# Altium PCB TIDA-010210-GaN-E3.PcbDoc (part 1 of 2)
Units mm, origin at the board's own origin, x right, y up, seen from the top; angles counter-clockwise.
Board outline 75 x 60 mm, 4 copper layers (Top Layer, MidLayer1, MidLayer2, Bottom Layer), stack 1.554 mm thick; 107 components, 49 nets, 409 pads, 513 vias.
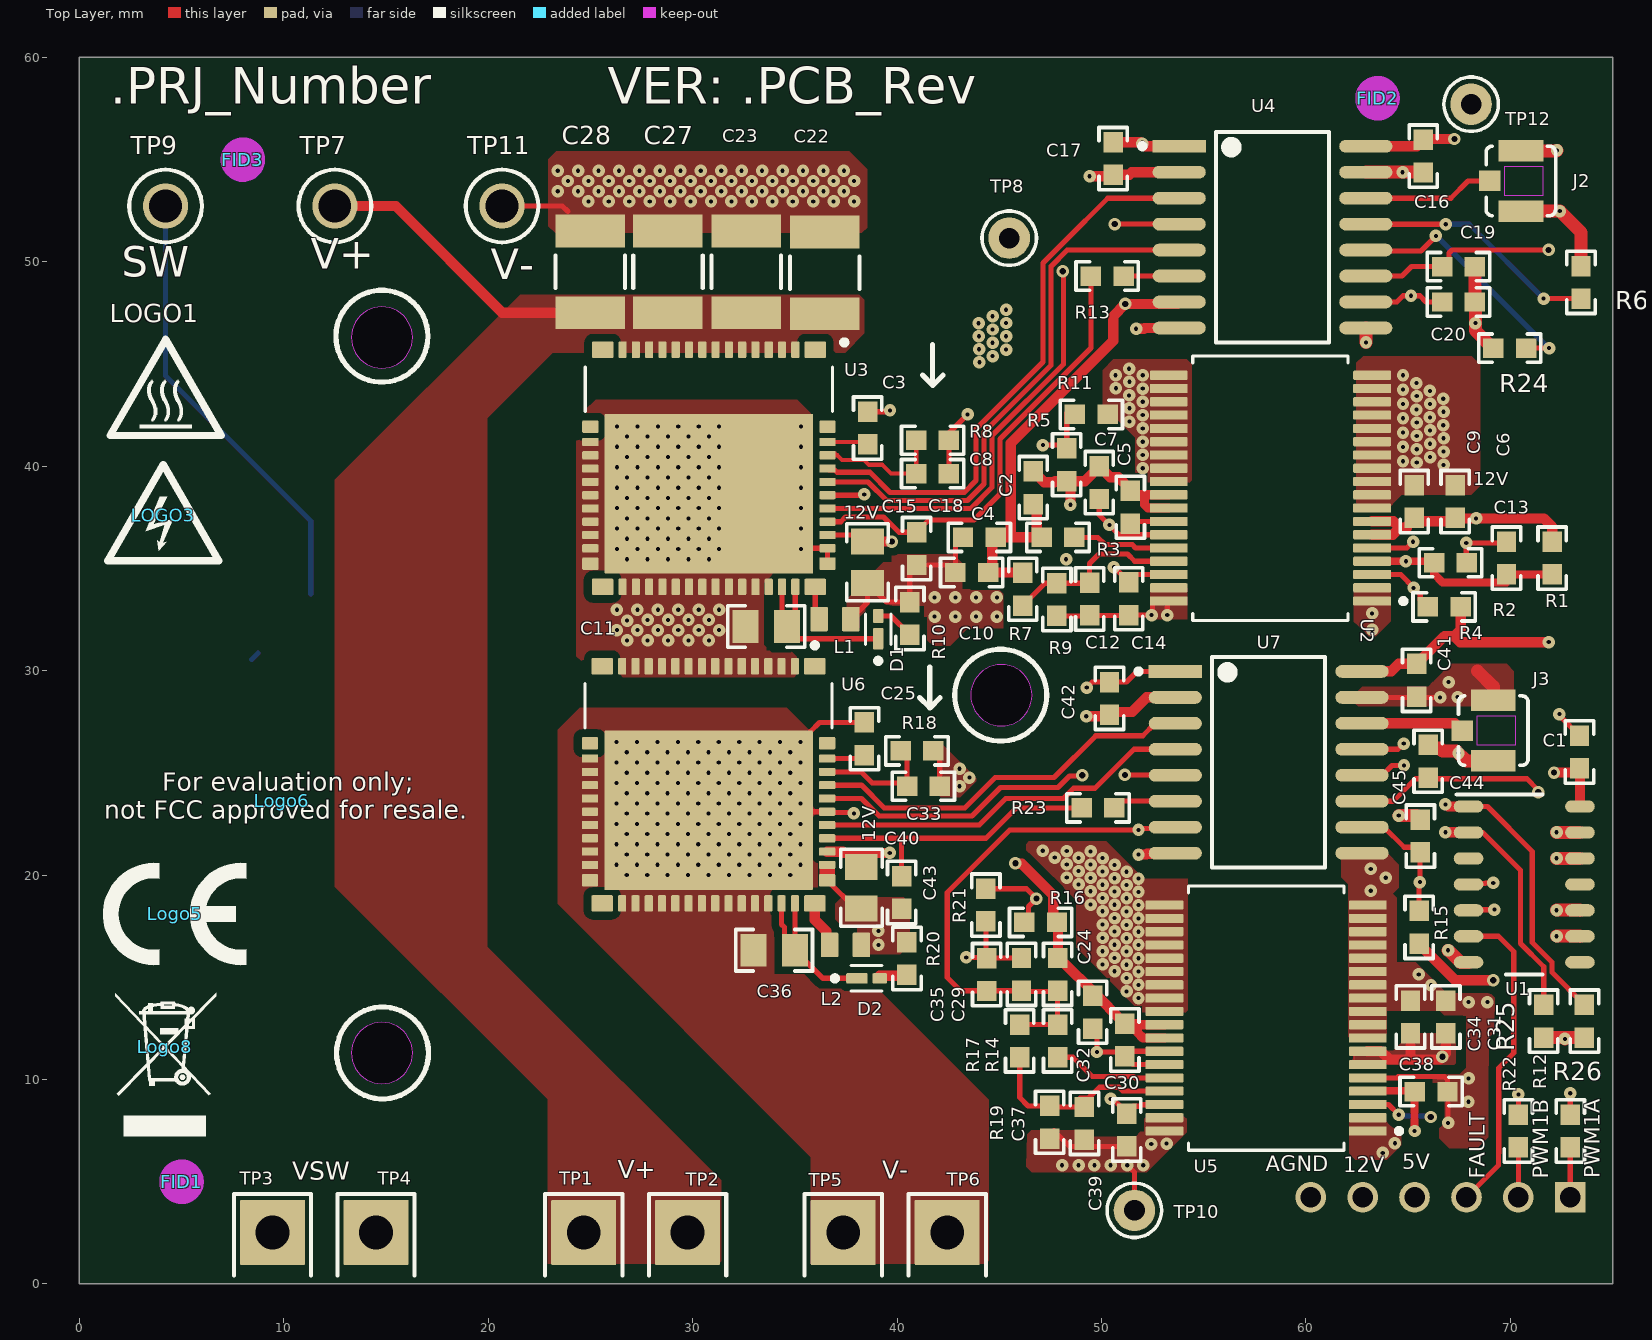
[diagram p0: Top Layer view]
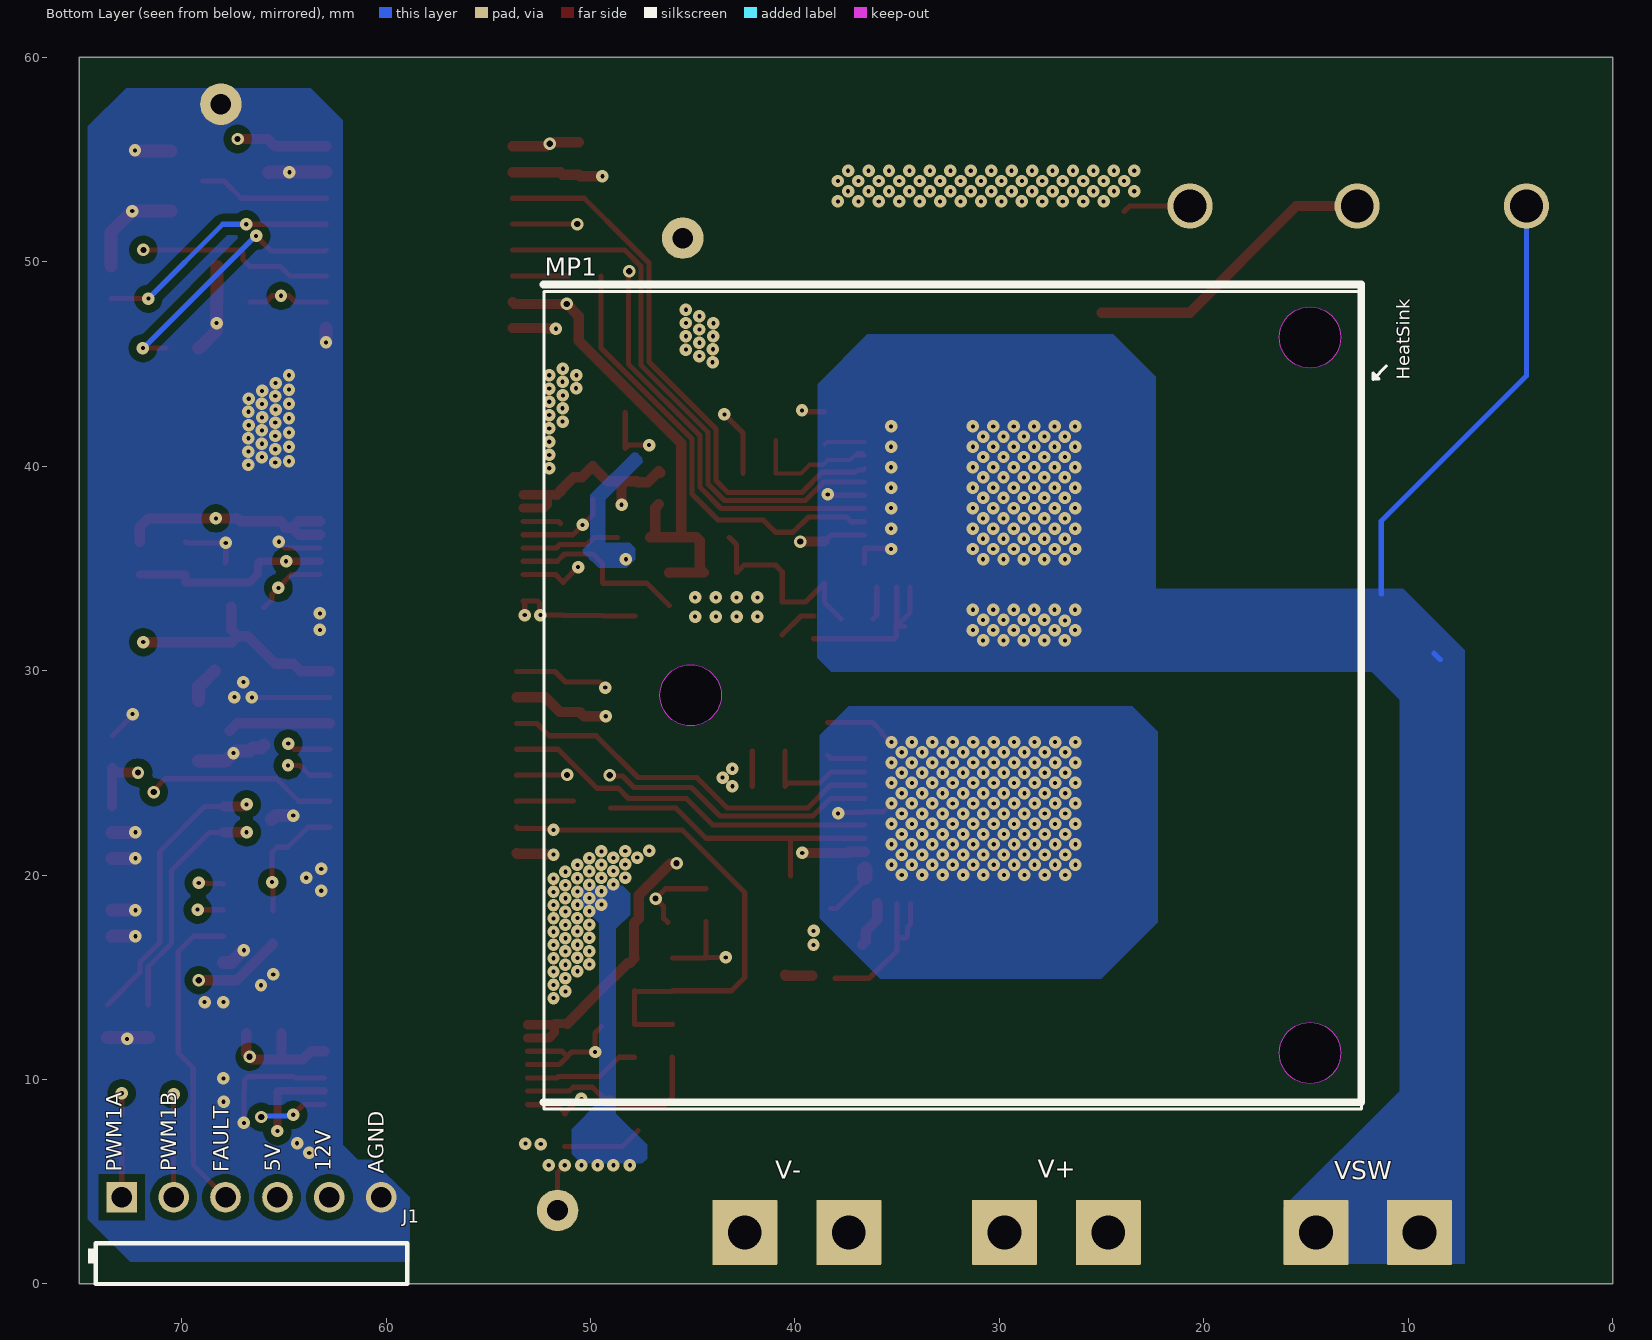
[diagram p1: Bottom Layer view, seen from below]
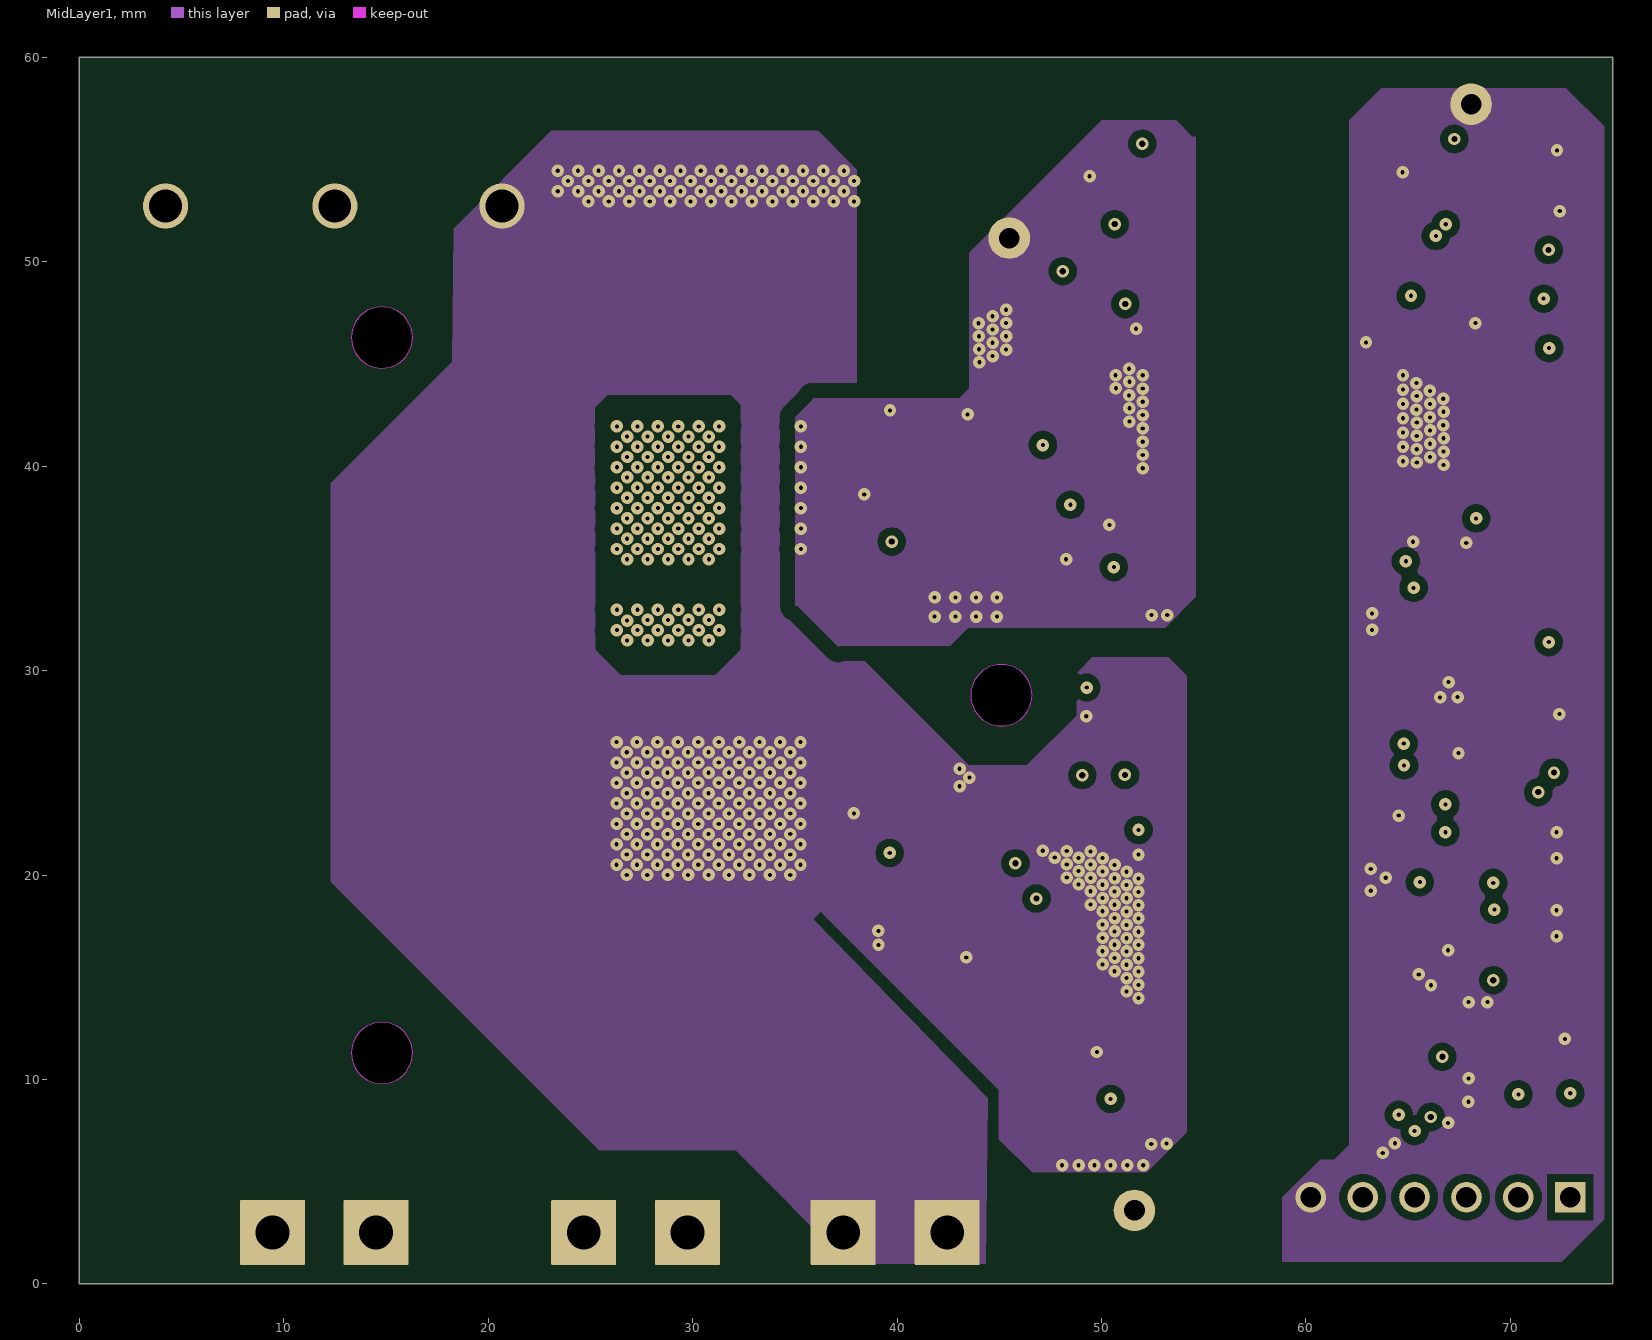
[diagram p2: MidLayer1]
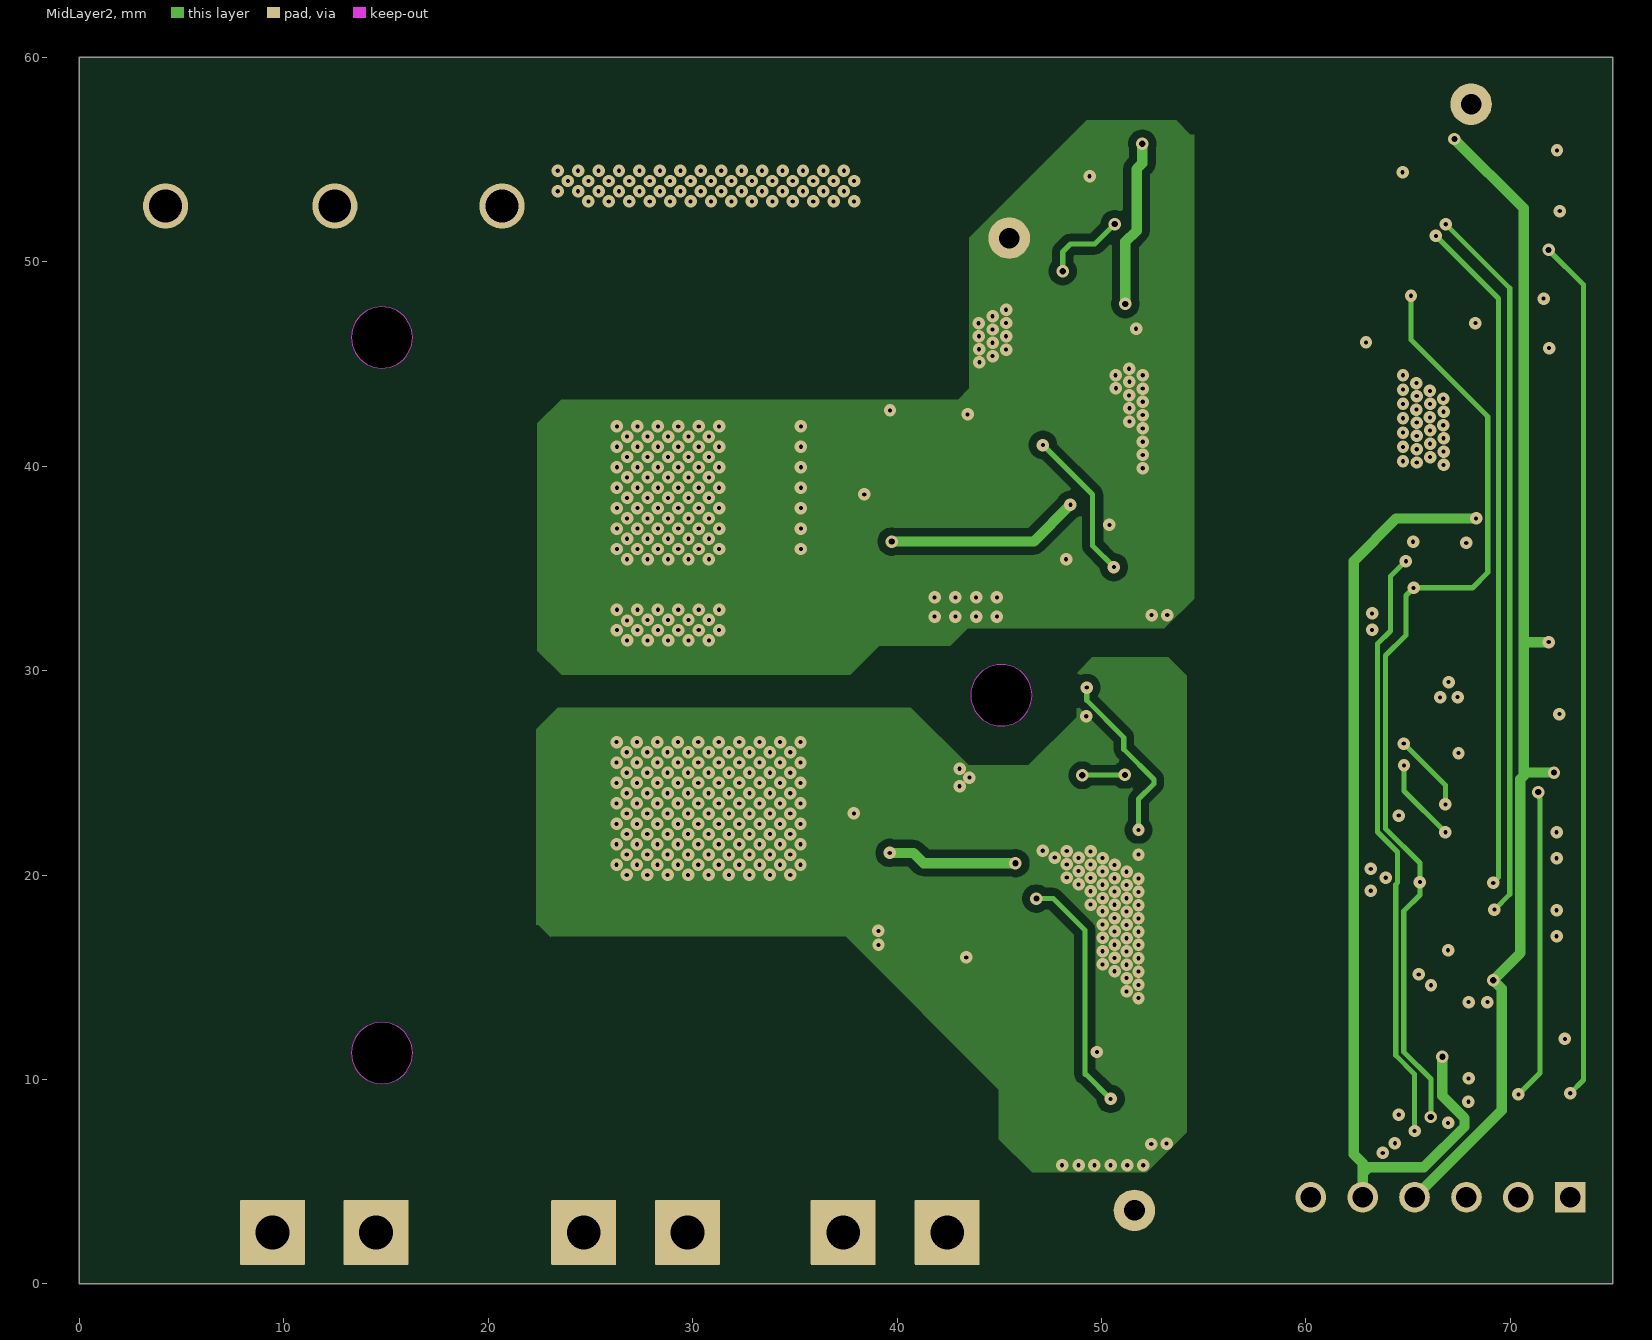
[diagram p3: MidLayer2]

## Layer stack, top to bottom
Top Solder: solder mask 0.0102, Solder Resist, Dk 3.5
Top Layer: signal copper 0.0711
Dielectric1: core 0.254, FR-4 High Tg, Dk 4.8
MidLayer1: signal copper 0.0711
Dielectric2: prepreg 0.762, FR-4 High Tg, Dk 4.8
MidLayer2: signal copper 0.0711
Dielectric3: core 0.254, FR-4 High Tg, Dk 4.8
Bottom Layer: signal copper 0.0711
Bottom Solder: solder mask 0.0102, Solder Resist, Dk 3.5

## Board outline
0,0 0,60 75,60 75,0
cut-out: 13.3,46.3 ccw(c14.8,46.3) 14.8,44.8 ccw(c14.8,46.3) 16.3,46.3 ccw(c14.8,46.3) 14.8,47.8 ccw(c14.8,46.3)
cut-out: 13.3,11.3 ccw(c14.8,11.3) 14.8,9.8 ccw(c14.8,11.3) 16.3,11.3 ccw(c14.8,11.3) 14.8,12.8 ccw(c14.8,11.3)
cut-out: 43.6,28.8 ccw(c45.1,28.8) 45.1,27.3 ccw(c45.1,28.8) 46.6,28.8 ccw(c45.1,28.8) 45.1,30.3 ccw(c45.1,28.8)

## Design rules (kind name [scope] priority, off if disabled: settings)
AcuteAngle [All] p1: minimum=4.50000000000000E+0001 checktracksonly=FALSE
AssemblyTestPointUsage [All] p1: valid=2
Clearance "Basic ISO to HV" [InNetClass('ISO') vs InNetClass('HV_PLUS')  or InNetClass('HV_MINUS') or InNetClass('HV_BRIDGE_POINT')] p1: gap=4 ignorepadtopadclearanceinfootprint=FALSE
Clearance "HVPLUS TO HVMINUS" [InNetClass('HV_PLUS') vs InNetClass('HV_MINUS')] p2: gap=2.2 ignorepadtopadclearanceinfootprint=FALSE
Clearance "HVPHVN to BR" [InNetClass('HV_PLUS')  or InNetClass('HV_MINUS') vs InNetClass('HV_BRIDGE_POINT')] p3: gap=0.762 ignorepadtopadclearanceinfootprint=FALSE
Clearance Clearance_BoardEdge_MountingHoles [OnCopper and InComponentClass('Mounting Holes') vs IsKeepOut] p4: gap=0.508 ignorepadtopadclearanceinfootprint=FALSE except(0: Arc-Hole Track-Hole SMDPad-Hole THPad-Hole Via-Hole Fill-Hole Poly-Hole Region-Hole Text-Hole)
Clearance Clearance_HV2_Mid1 [OnMid And InNetClass('VSWNET') vs (OnMultiLayer Or OnMid) And Not InNetClass('VSWNET')] p5: gap=0.508 ignorepadtopadclearanceinfootprint=FALSE except(0: Arc-Hole Track-Hole SMDPad-Hole THPad-Hole Via-Hole Fill-Hole Poly-Hole Region-Hole Text-Hole)
Clearance Clearance_HV2_Mid2 [(OnMultiLayer Or OnMid) And InNetClass('VSWNET') vs OnMid And Not InNetClass('VSWNET')] p6: gap=0.508 ignorepadtopadclearanceinfootprint=FALSE except(0: Arc-Hole Track-Hole SMDPad-Hole THPad-Hole Via-Hole Fill-Hole Poly-Hole Region-Hole Text-Hole)
Clearance Clearance_HV1_Mid1 [(OnMultiLayer Or OnMid) And InNetClass('VHV') vs OnMid And Not InNetClass('VHV')] p7: gap=0.508 ignorepadtopadclearanceinfootprint=FALSE except(0: Arc-Hole Track-Hole SMDPad-Hole THPad-Hole Via-Hole Fill-Hole Poly-Hole Region-Hole Text-Hole)
Clearance Clearance_HV1_Mid2 [OnMid And InNetClass('VHV') vs (OnMultiLayer Or OnMid) And Not InNetClass('VHV')] p8: gap=0.508 ignorepadtopadclearanceinfootprint=FALSE except(0: Arc-Hole Track-Hole SMDPad-Hole THPad-Hole Via-Hole Fill-Hole Poly-Hole Region-Hole Text-Hole)
Clearance Clearance_HV1 [InNetClass('VHV') vs NOT InNetClass('VHV')] p9: gap=1.524 ignorepadtopadclearanceinfootprint=FALSE except(0: Arc-Hole Track-Hole SMDPad-Hole THPad-Hole Via-Hole Fill-Hole Poly-Hole Region-Hole Text-Hole; 1.016: THPad-Fill THPad-Poly THPad-Region)
Clearance "Clearance_Poly to All" [inpoly] p10: gap=0.381 ignorepadtopadclearanceinfootprint=FALSE
Clearance [All] p11: gap=0.14 ignorepadtopadclearanceinfootprint=FALSE except(0: Arc-Arc Arc-SMDPad Arc-THPad Arc-Hole Track-Hole SMDPad-Hole THPad-Hole Via-Hole Fill-Hole Poly-Hole Region-Hole Text-Hole)
ComponentClearance ComponentClearance_Shunt [InComponentClass('Header') vs InComponentClass('Shunt')] p1: gap=0 collisioncheckmode=3 verticalgap=0 showdistances=FALSE
ComponentClearance ComponentClearance_MountingHoles_FiducialMarks [InComponentClass('Mounting Holes') vs InComponentClass('FiducialMark')] p2: gap=1.27 collisioncheckmode=3 verticalgap=0.254 showdistances=FALSE
ComponentClearance ComponentClearance_Logo [InComponentClass('Logo')] p3: gap=0 collisioncheckmode=3 verticalgap=0.254 showdistances=FALSE
ComponentClearance ComponentClearance_ScrewToNut [(HasFootprint('NY PMS 440 0025 PH')) vs (HasFootprint('Keystone_1902C'))] p4: gap=0.127 collisioncheckmode=3 verticalgap=0.254 showdistances=FALSE
ComponentClearance ComponentClearance_MountingHoles [InComponentClass('Mounting Holes')] p5: gap=6.35 collisioncheckmode=3 verticalgap=2540 showdistances=FALSE
ComponentClearance ComponentClearance_SmallPassives [HasFootprint('0201*') or HasFootprint('0402*') or HasFootprint('0508') or HasFootprint('0603*') or HasFootprint('0612') or HasFootprint('0805*') or HasFootprint('0815*') or HasFootprint('0830*') or HasFootprint('1206*') or HasFootprint('1210*') or HasFootprint('1808*') or HasFootprint('1812*') or HasFootprint('1825*') or HasFootprint('2010*') or HasFootprint('2220*') or HasFootprint('2225*') or HasFootprint('2512*') or HasFootprint('2728*') or HasFootprint('3518*') vs HasFootprint('0201*') or HasFootprint('0402*') or HasFootprint('0508') or HasFootprint('0603*') or HasFootprint('0612') or HasFootprint('0805*') or HasFootprint('0815*') or HasFootprint('0830*') or HasFootprint('1206*') or HasFootprint('1210*') or HasFootprint('1808*') or HasFootprint('1812*') or HasFootprint('1825*') or HasFootprint('2010*') or HasFootprint('2220*') or HasFootprint('2225*') or HasFootprint('2512*') or HasFootprint('2728*') or HasFootprint('3518*')] p6: gap=0.381 collisioncheckmode=3 verticalgap=0.254 showdistances=FALSE
ComponentClearance ComponentClearance_THtoSMT [IsThruComponent vs IsSMTComponent] p7: gap=0.762 collisioncheckmode=3 verticalgap=0.762 showdistances=FALSE
ComponentClearance ComponentClearance_THtoTH [IsThruComponent vs IsThruComponent] p8: gap=0 collisioncheckmode=3 verticalgap=0.254 showdistances=FALSE
ComponentClearance [All] p9: gap=0.381 collisioncheckmode=3 verticalgap=0.254 showdistances=FALSE
DiffPairsRouting [All] p1: maxlimit=2.54 minlimit=0.254 mostfreqgap=0.254 toplayer_minwidth=0.381 toplayer_maxwidth=0.381 toplayer_prefwidth=0.381 midlayer1_minwidth=0.381 midlayer1_maxwidth=0.381 midlayer1_prefwidth=0.381 midlayer2_minwidth=0.381 midlayer2_maxwidth=0.381 midlayer2_prefwidth=0.381 bottomlayer_minwidth=0.381 bottomlayer_maxwidth=0.381 bottomlayer_prefwidth=0.381 maxuncoupledlength=25.4
FabricationTestPointUsage TestPointUsage [All] p1: valid=2 allowmultiple=FALSE
FabricationTestpoint Testpoint [All] p1: side=3 testpointundercomponent=TRUE minsize=1.016 maxsize=2.54 preferedsize=1.524 minholesize=0 maxholesize=1.016 preferedholesize=0.813 testpointgrid=0.025 allowsidetop=TRUE allowsidebottom=TRUE usegrid=TRUE gridtolerance=0
FanoutControl Fanout_LCC [IsLCC] p1: bgadir=Out bgaviamode=Centered fanoutstyle=Auto fanoutdirection=Alternating viagrid=0.025 // Fanout_LCC (Default Rule)
FanoutControl Fanout_BGA [IsBGA] p2: bgadir=Out bgaviamode=Centered fanoutstyle=Auto fanoutdirection=Alternating viagrid=0.025 // Fanout_BGA (Default Rule)
FanoutControl Fanout_Default [All] p4: bgadir=Out bgaviamode=Centered fanoutstyle=Auto fanoutdirection=Alternating viagrid=0.025 // Fanout_Default (Default Rule)
FanoutControl Fanout_Small [(CompPinCount < 5)] p5: bgadir=Out bgaviamode=Centered fanoutstyle=Auto fanoutdirection=OutThenIn viagrid=0.025 // Fanout_Small (Default Rule)
HoleSize [All] p1: absolutevalues=TRUE maxlimit=6.375 minlimit=0.152 maxpercent=80.000 minpercent=20.000
MinimumAnnularRing MinimumAnnularRing_ThermalPadVias [IsVia and InAnyComponent] p1 off: minimumring=0.127
MinimumAnnularRing [IsVia] p2 off: minimumring=0.127
MinimumSolderMaskSliver MinimumSolderMaskSliver_Logo [InComponentClass('Logo') vs InComponentClass('Logo')] p1: minsoldermaskwidth=0.018
MinimumSolderMaskSliver [All] p2: minsoldermaskwidth=0.1
PlaneConnect [All] p1: planeconnectstyle=Relief reliefexpansion=0.254 reliefentries=4 reliefconductorwidth=0.254 reliefairgap=0.254
PolygonConnect [All] p1: connectstyle=Direct reliefconductorwidth=0.254 reliefentries=4 polygonreliefangle="90 Angle" airgapwidth=0.254
RoutingVias ThermalPadVias [IsVia and InAnyComponent] p1: holewidth=0.203 width=0.406 viastyle="Through Hole" minholewidth=0.203 minwidth=0.406 maxholewidth=0.203 maxwidth=0.406
RoutingVias [All] p2: holewidth=0.305 width=0.61 viastyle="Through Hole" minholewidth=0.152 minwidth=0.254 maxholewidth=1.016 maxwidth=1.651
SMDToCorner [All] p1: distance=30000
SilkToSilkClearance [All] p1: silktosilkclearance=0
SilkToSolderMaskClearance SilkscreenOverComponentPads [IsPad] p1: minsilkscreentomaskgap=0.127 clearancetoexposedcopper=TRUE
SolderMaskExpansion [All] p1: expansion=0.05 istentingtop=FALSE
Width [All] p1: maxlimit=25.4 minlimit=0.152 preferedwidth=0.635 toplayer_prefwidth=0.305 midlayer1_prefwidth=0.254 midlayer2_prefwidth=0.254 minimp=50.000000 maximp=50.000000 favimp=50.000000 checkconnectedcopper=TRUE
16 further rules are at their usual default settings.

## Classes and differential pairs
net class HV_PLUS: High_Rail NetU3_1 NetU3_16
net class HV_MINUS: 5V_LS 12V_LS Low_Rail NetC25_2 NetC33_2 NetC36_2 NetC37_1 NetC39_1 NetC43_1 NetD2_2 NetL2_2 NetR14_1 NetR23_1 NetU5_17 NetU5_28 NetU5_54 NetU6_48 NetU6_50 NetU6_51
net class ISO: 5V_ISO 12V_ISO EN_Supply_Driver F\A\U\L\T\_\H\S\_\I\S\O\ F\A\U\L\T\_\L\S\_\I\S\O\ GND_ISO NetC19_1 NetC20_1 NetC44_1 NetJ1_3 NetU1_3 NetU1_8 NetU1_11 O\C\_\H\S\_\I\S\O\ O\C\_\L\S\_\I\S\O\ PWM_HS_ISO PWM_LS_ISO TEMP_HS_ISO TEMP_LS_ISO
net class HV_BRIDGE_POINT: 5V_HS 12V_HS NetC3_2 NetC8_2 NetC11_2 NetC12_1 NetC14_1 NetC18_1 NetD1_2 NetL1_2 NetR3_1 NetR13_1 NetU3_17 NetU3_28 NetU3_48 NetU3_50 NetU3_51 NetU3_54 NetU5_1 NetU5_16 SW_Rail
component class U_Half_Bridge: C2 C3 C4 C5 C6 C7 C8 C9 C10 C11 C12 C13 C14 C15 C16 C17 C18 C19 C20 C22 C23 C24 C25 C27 C28 C29 C30 C31 C32 C33 C34 C35 C36 C37 C38 C39 C40 C41 C42 C43 C44 C45 D1 D2 "Heat Sink1" L1 L2 R3 R4 R5 R7 R8 R9 R10 R11 R12 R13 R14 R15 R16 R17 R18 R19 R20 R21 R22 R23 "Thermal Pad1" TP7 TP8 TP9 TP10 TP11 TP12 U2 U3 U4 U5 U6 U7
component class AssemblyNote: ZZ1 ZZ2 ZZ3
component class FiducialMark: FID1 FID2 FID3
component class "Cover Sheet-Pg1": !PCB C1 FID1 FID2 FID3 HS1 J1 J2 J3 LOGO1 LOGO3 Logo5 Logo6 Logo8 MP1 R1 R2 R6 R24 R25 R26 TIM1 TP1 TP2 TP3 TP4 TP5 TP6 U1 ZZ1 ZZ2 ZZ3
component class Header: J1

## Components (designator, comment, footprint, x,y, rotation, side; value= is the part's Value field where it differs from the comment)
C1 "06033C104JAT2A" 0603 73.381,26.018 r90 top value=0.1uF
C2 "C1608X6S1C155K080AC" 0603 46.657,38.952 r270 top value=1.5uF
C3 "06033C104JAT2A" 0603 38.555,41.867 r270 top value=0.1uF
C4 "06033C104JAT2A" 0603 44.024,36.519 r180 top value=0.1uF
C5 "06033C104JAT2A" 0603 51.411,37.994 r270 top value=0.1uF
C6 "GRM188C71E225KE11D" 0603 67.297,38.271 r90 top value=2.2uF
C7 "GRM188C71E225KE11D" 0603 49.889,39.198 r270 top value=2.2uF
C8 "C0603C102F3GACTU" 0603 41.736,39.639 r180 top value=1000pF
C9 "GRM1885C1H151JA01D" 0603 65.297,38.271 r90 top value=150pF
C10 "GRM188C71E225KE11D" 0603 43.649,34.802 r180 top value=2.2uF
C11 "GRM21BR71E225KA73L" 0805_HV 33.596,32.166 r0 top value=2.2uF
C12 "C0603X332K5RACTU" 0603 49.414,33.503 r270 top value=3300pF
C13 "SR0603X7R103K1NT95(F)#M123A" 0603 67.069,35.277 r0 top value=0.01uF
C14 "C0603X332K5RACTU" 0603 51.329,33.518 r270 top value=3300pF
C15 "GRM219B31E106MA12" 0805_HV 38.555,35.301 r270 top value=10uF
C16 "06033C104JAT2A" 0603 65.738,55.169 r270 top value=0.1uF
C17 "06033C104JAT2A" 0603 50.564,55.05 r270 top value=0.1uF
C18 "C0603C221K5GACTU" 0603 40.955,35.969 r270 top value=220pF
C19 "C0603C221K5GACTU" 0603 67.462,49.763 r0 top value=220pF
C20 "SR0603X7R103K1NT95(F)#M123A" 0603 67.462,48.033 r0 top value=0.01uF
C22 "C1812W104KDRACTU" 1812_254 36.461,49.463 r90 top value=0.1uF
C23 "C1812W104KDRACTU" 1812_254 32.629,49.51 r90 top value=0.1uF
C24 "C1608X6S1C155K080AC" 0603 47.853,15.146 r270 top value=1.5uF
C25 "06033C104JAT2A" 0603 38.401,26.669 r270 top value=0.1uF
C27 "C1812W104KDRACTU" 1812_254 28.792,49.51 r90 top value=0.1uF
C28 "C1812W104KDRACTU" 1812_254 24.982,49.51 r90 top value=0.1uF
C29 "06033C104JAT2A" 0603 46.084,15.146 r90 top value=0.1uF
C30 "06033C104JAT2A" 0603 51.138,11.935 r270 top value=0.1uF
C31 "GRM188C71E225KE11D" 0603 66.841,13.064 r90 top value=2.2uF
C32 "GRM188C71E225KE11D" 0603 49.563,13.291 r270 top value=2.2uF
C33 "C0603C102F3GACTU" 0603 41.286,24.349 r180 top value=1000pF
C34 "GRM1885C1H151JA01D" 0603 65.114,13.064 r90 top value=150pF
C35 "GRM188C71E225KE11D" 0603 44.382,15.131 r90 top value=2.2uF
C36 "GRM21BR71E225KA73L" 0805_HV 33.984,16.322 r0 top value=2.2uF
C37 "C0603X332K5RACTU" 0603 49.163,7.856 r270 top value=3300pF
C38 "SR0603X7R103K1NT95(F)#M123A" 0603 66.122,9.413 r0 top value=0.01uF
C39 "C0603X332K5RACTU" 0603 51.234,7.529 r270 top value=3300pF
C40 "GRM219B31E106MA12" 0805_HV 38.251,19.381 r270 top value=10uF
C41 "06033C104JAT2A" 0603 65.415,29.529 r270 top value=0.1uF
C42 "06033C104JAT2A" 0603 50.39,28.644 r270 top value=0.1uF
C43 "C0603C221K5GACTU" 0603 40.218,19.151 r270 top value=220pF
C44 "C0603C221K5GACTU" 0603 65.977,25.568 r90 top value=220pF
C45 "SR0603X7R103K1NT95(F)#M123A" 0603 65.598,21.909 r90 top value=0.01uF
D1 "KG DELLS1.22-JGKH-24" "FP-KG DELLS1.22-JGKH-24_0603-MFG" 39.075,32.033 r90 top
D2 "KG DELLS1.22-JGKH-24" "FP-KG DELLS1.22-JGKH-24_0603-MFG" 38.505,14.95 r0 top
FID1 "Fiducial" Fiducial6.4-20 5,5 r0 top
FID2 "Fiducial" Fiducial6.4-20 63.5,58 r0 top
FID3 "Fiducial" Fiducial6.4-20 8,55 r0 top
J1 "90121-0766" Molex_90121-0766 66.581,4.242 r180 bottom
J2 "U.FL-R-SMT-1(01)" CONN_UFL-R-SMT-1 70.51,53.956 r0 top
J3 "U.FL-R-SMT-1(01)" CONN_UFL-R-SMT-1 69.162,27.068 r0 top
L1 "74404020100" WE-LQS_2010 36.961,32.522 r180 top value=10uH
L2 "74404020100" WE-LQS_2010 37.476,16.582 r180 top value=10uH
LOGO1 "CAUTION HOT SURFACE" IEC_HotSurface_Small 4.216,43.863 r0 top
LOGO3 "DANGER HIGH VOLTAGE" IEC_HighVoltage_Small 4.102,37.61 r0 top
Logo5 "CE Mark" CE_Mark_5mm 4.661,18.098 r0 top
Logo6 "FCC disclaimer" FCC_disclaimer_stacked 9.898,23.645 r0 top
Logo8 "WEEE logo" WEEE_Minimum 4.178,11.593 r0 top
MP1 "APF40-40-13CB/A01" FP-APF40-40-13CB-A01_HEATSINK_40MM0_40MM0-MFG 32.275,28.55 r180 bottom
R1 "RC0603FR-0712KL" 0603 72.046,35.507 r90 top value=12.0k
R2 "RC0603FR-072K7L" 0603 69.81,35.507 r270 top value=2.70k
R3 "RC0603JR-071KL" 0603 47.872,36.52 r180 top value=1.0k
R4 "RC0603FR-0712KL" 0603 66.761,33.125 r180 top value=12.0k
R5 "M55342K12B10E0T" 0603 48.296,40.073 r90 top value=10.0k
R6 "CR0603-JW-472GLF" 0603 73.455,48.993 r270 top value=4.7k
R7 "M55342K12B10E0T" 0603 46.147,33.983 r90 top value=10.0k
R8 "RC0603FR-0733KL" 0603 41.736,41.271 r0 top value=33.0k
R9 "M55342K12B10E0T" 0603 47.817,33.478 r90 top value=10.0k
R10 "RC0603JR-075K6L" 0603 40.623,32.553 r270 top value=5.6k
R11 "RC0603FR-072K61L" 0603 49.5,42.534 r180 top value=2.61k
R12 "RC0603FR-0756RL" 0603 72.931,7.482 r90 top value=56.0
R13 "RC0603FR-0756RL" 0603 50.278,49.303 r180 top value=56.0
R14 "RC0603JR-071KL" 0603 47.853,11.891 r90 top value=1.0k
R15 "RC0603FR-0712KL" 0603 65.534,17.446 r270 top value=12.0k
R16 "M55342K12B10E0T" 0603 47.022,17.692 r180 top value=10.0k
R17 "M55342K12B10E0T" 0603 45.996,11.891 r90 top value=10.0k
R18 "RC0603FR-0733KL" 0603 40.97,26.074 r0 top value=33.0k
R19 "M55342K12B10E0T" 0603 47.462,7.912 r90 top value=10.0k
R20 "RC0603JR-075K6L" 0603 40.48,15.921 r270 top value=5.6k
R21 "RC0603FR-072K61L" 0603 44.341,18.532 r90 top value=2.61k
R22 "RC0603FR-0756RL" 0603 70.391,7.482 r90 top value=56.0
R23 "RC0603FR-0756RL" 0603 49.826,23.289 r180 top value=56.0
R24 "CR0603-JW-472GLF" 0603 69.969,45.78 r0 top value=4.7k
R25 "CR0603-JW-472GLF" 0603 71.63,12.853 r90 top value=4.7k
R26 "CR0603-JW-472GLF" 0603 73.622,12.853 r90 top value=4.7k
TP1 "3620-2-32-15-00-00-08-0" Mill-Max_3620-2-32-xx-00-00-08-0 24.671,0 r0 top
TP2 "3620-2-32-15-00-00-08-0" Mill-Max_3620-2-32-xx-00-00-08-0 29.751,0 r0 top
TP3 "3620-2-32-15-00-00-08-0" Mill-Max_3620-2-32-xx-00-00-08-0 9.449,0 r0 top
TP4 "3620-2-32-15-00-00-08-0" Mill-Max_3620-2-32-xx-00-00-08-0 14.511,0 r0 top
TP5 "3620-2-32-15-00-00-08-0" Mill-Max_3620-2-32-xx-00-00-08-0 37.363,0 r0 top
TP6 "3620-2-32-15-00-00-08-0" Mill-Max_3620-2-32-xx-00-00-08-0 42.451,0 r0 top
TP7 "5005" Keystone5005 12.497,52.73 r0 top
TP8 "5001" Keystone5001 45.484,51.158 r90 top
TP9 "5008" Keystone5008 4.216,52.73 r0 top
TP10 "5001" Keystone5001 51.606,3.601 r90 top
TP11 "5006" Keystone5006 20.676,52.73 r0 top
TP12 "5001" Keystone5001 68.079,57.71 r90 top
U1 "SN74AS21D" D0014A_N 70.677,19.546 r0 top
U2 "UCC14150DWNQ1" DWN0036A-MFG 58.261,38.927 r180 top locked
U3 "LMG3422R030" RQZ0054A-MFG-NV 30.796,39.9 r270 top locked
U4 "ISO7741FDW" FP-DW0016A-IPC_A 58.363,51.208 r0 top locked
U5 "UCC14150DWNQ1" DWN0036A-MFG 58.051,13.007 r180 top locked
U6 "LMG3422R030" RQZ0054A-MFG-NV 30.775,24.415 r270 top locked
U7 "ISO7741FDW" FP-DW0016A-IPC_A 58.175,25.518 r0 top locked
ZZ1 "These assemblies are ESD sensitive, ESD precautions shall be observed." AssemblyNote 1.778,67.963 r0 top
ZZ2 "These assemblies must be clean and free from flux and all contaminants. Use of no clean flux is not acceptable." AssemblyNote 1.778,65.677 r0 top
ZZ3 "These assemblies must comply with workmanship standards IPC-A-610 Class 2, unless otherwise specified." AssemblyNote 1.778,62.756 r0 top

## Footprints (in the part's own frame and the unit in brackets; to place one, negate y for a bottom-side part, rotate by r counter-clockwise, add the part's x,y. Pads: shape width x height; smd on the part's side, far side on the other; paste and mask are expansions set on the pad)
0603 [mm] "0603 from SM-752 data"
  rect 1x0.95 smd: 1(-0.8,0) 2(0.8,0)
  silkscreen extent -1.52,-0.69 1.52,0.69, body extent -0.87,-0.47 0.87,0.47, height 1
0805_HV [mil] "0805 with 30mil clearance between pads"
  rect 50x63 smd: 1(-40,0) 2(40,0)
  silkscreen extent -74,-40 74,40, body extent -43,-29 43,29, height 57
1812_254 [mm] "SMD, 2-Leads, Body 4.8x3.4mm"
  rect 1.6x3.4 smd: 1(-2,0) 2(2,0)
  silkscreen extent -0.8,-1.7 0.8,1.7, body extent -2.4,-1.7 2.4,1.7, height 2.54
AssemblyNote [mm] "Assembly Note"
CE_Mark_5mm [mm] "Minimum text height for CE Mark"
  silkscreen extent -3.5,-2.5 3.5,2.5
CONN_UFL-R-SMT-1 [mm] "Hirose recommended land pattern http://www.hirose.co.jp/cataloge_hp/e32119372.pdf 2009.2"
  rect 1.05x1 smd paste-0.1 mask-0.1: 1(-1.525,0)
  rect 2.2x1.05 smd paste-2 mask-2: 2(0,1.475) 3(0,-1.475)
  rect 2x0.9 on Top Paste: 2(0,1.5) 3(0,-1.5)
  rect 2x0.9 on Top Solder: 2(0,1.5) 3(0,-1.5)
  Top Layer keep-out region: -0.8,-0.7 1.1,-0.7 1.1,0.7 -0.8,0.7
  silkscreen extent -1.7,-1.7 1.7,1.7, body extent -1.55,-1.5 1.55,1.5, height 1.27
D0014A_N [mm] "SOIC, 14-Leads, Body 8.7x3.9mm, Pitch 1.27mm, IPC Medium Density"
  oval 1.45x0.6 smd: 1(-2.725,3.81) 2(-2.725,2.54) 3(-2.725,1.27) 4(-2.725,0) 5(-2.725,-1.27) 6(-2.725,-2.54) 7(-2.725,-3.81) 8(2.725,-3.81) 9(2.725,-2.54) 10(2.725,-1.27) 11(2.725,0) 12(2.725,1.27) 13(2.725,2.54) 14(2.725,3.81)
  silkscreen extent -3.3,-4.4 0.9,4.4, body extent -3.02,-4.32 3.02,4.32, height 1.6
DWN0036A-MFG [mm]
  rrect22% 1.85x0.45 smd paste+0 mask+0: 1(-4.975,5.525) 2(-4.975,4.875) 3(-4.975,4.225) 4(-4.975,3.575) 5(-4.975,2.925) 6(-4.975,2.275) 7(-4.975,1.625) 8(-4.975,0.975) 9(-4.975,0.325) 10(-4.975,-0.325) 11(-4.975,-0.975) 12(-4.975,-1.625) 13(-4.975,-2.275) 14(-4.975,-2.925) 15(-4.975,-3.575) 16(-4.975,-4.225) 17(-4.975,-4.875) 18(-4.975,-5.525) 19(4.975,-5.525) 20(4.975,-4.875) 21(4.975,-4.225) 22(4.975,-3.575) 23(4.975,-2.925) 24(4.975,-2.275) 25(4.975,-1.625) 26(4.975,-0.975) 27(4.975,-0.325) 28(4.975,0.325) 29(4.975,0.975) 30(4.975,1.625) 31(4.975,2.275) 32(4.975,2.925) 33(4.975,3.575) 34(4.975,4.225) 35(4.975,4.875) 36(4.975,5.525)
  silkscreen extent -6.63,-6.47 3.8,6.47, body extent -6,-6.72 6,6.72, height 0.25
FCC_disclaimer_stacked [mm]
Fiducial6.4-20 [mm]
  round 0.635 smd mask+0.683: 1(0,0)
  Top Layer keep-out circle w1.178: c0,0 r0.5
FP-APF40-40-13CB-A01_HEATSINK_40MM0_40MM0-MFG [mm]
  silkscreen extent -20,-20 20,20, body extent -20,-20 20,20, height 12.7
FP-DW0016A-IPC_A [mm]
  rect 2.603x0.622 smd paste+0 mask+0: 1(-4.565,4.445)
  rrect100% 2.603x0.622 smd paste+0 mask+0: 2(-4.565,3.175) 3(-4.565,1.905) 4(-4.565,0.635) 5(-4.565,-0.635) 6(-4.565,-1.905) 7(-4.565,-3.175) 8(-4.565,-4.445) 9(4.565,-4.445) 10(4.565,-3.175) 11(4.565,-1.905) 12(4.565,-0.635) 13(4.565,0.635) 14(4.565,1.905) 15(4.565,3.175) 16(4.565,4.445)
  silkscreen extent -6.49,-5.15 2.76,5.15, body extent -6.37,-5.65 6.37,5.65, height 0.25
"FP-KG DELLS1.22-JGKH-24_0603-MFG" [mm]
  rrect20% 1.05x0.5 smd paste-1000 mask+0: 1(-0.47,0)
  rrect20% 0.7x0.5 smd paste-1000 mask+0: 2(0.645,0)
  silkscreen extent -1.67,-0.63 0.75,0.63, body extent -0.8,-0.4 0.8,0.4, height 0.7
IEC_HighVoltage_Small [mm]
  silkscreen extent -2.72,-2.24 2.72,2.47
IEC_HotSurface_Small [mm]
  silkscreen extent -2.72,-2.36 2.72,2.35
Keystone5001 [mil] "For Keystone 500x miniature loop terminals"
  round 80 hole 40: 1(0,0)
  silkscreen extent -52,-52 52,52, body extent -49,-49 49,49, height 182
Keystone5005 [mil] "Keystone Compact loops"
  round 87 hole 63: 1(0,0)
  silkscreen extent -70,-70 70,70, body extent -63,-63 62,63, height 225
Keystone5006 [mil] "Keystone Compact loops"
  round 87 hole 63: 1(0,0)
  silkscreen extent -70,-70 70,70, body extent -63,-63 62,63, height 225
Keystone5008 [mil] "Keystone Compact loops"
  round 87 hole 63: 1(0,0)
  silkscreen extent -70,-70 70,70, body extent -63,-63 62,63, height 225
Mill-Max_3620-2-32-xx-00-00-08-0 [mm] "PCB Pin, 0.04\" DIA, R/A, Edge-Mount"
  rrect3% 3.18x3.18 hole 1.65: 1(0,2.52)
  silkscreen extent -1.89,0.41 1.89,4.41, body extent -1.59,-5.06 1.59,4.11, height 0.65
Molex_90121-0766 [mm] "Header, 2.54mm, 6x1, R/A, TH"
  rect 1.5x1.5 hole 1: 1(-6.35,0)
  round 1.5 hole 1: 2(-3.81,0) 3(-1.27,0) 4(1.27,0) 5(3.81,0) 6(6.35,0)
  silkscreen extent -8,-4.25 7.62,-2.25, body extent -7.62,-11 7.62,0.32, height 3.63
RQZ0054A-MFG-NV [mm]
  rrect13% 0.8x1.05 smd paste+0 mask+0: 1(-5.8,5.2) 16(-5.8,-5.2) 28(5.8,-5.2) 43(5.8,5.2)
  rrect25% 0.8x0.4 smd paste+0 mask+0: 2(-5.8,4.225) 3(-5.8,3.575) 4(-5.8,2.925) 5(-5.8,2.275) 6(-5.8,1.625) 7(-5.8,0.975) 8(-5.8,0.325) 9(-5.8,-0.325) 10(-5.8,-0.975) 11(-5.8,-1.625) 12(-5.8,-2.275) 13(-5.8,-2.925) 14(-5.8,-3.575) 15(-5.8,-4.225) 29(5.8,-4.225) 30(5.8,-3.575) 31(5.8,-2.925) 32(5.8,-2.275) 33(5.8,-1.625) 34(5.8,-0.975) 35(5.8,-0.325) 36(5.8,0.325) 37(5.8,0.975) 38(5.8,1.625) 39(5.8,2.275) 40(5.8,2.925) 41(5.8,3.575) 42(5.8,4.225)
  rrect17% 0.6x0.8 smd paste+0 mask+0: 17(-2.035,-5.8) 27(4.665,-5.8) 44(4.665,5.8) 54(-2.035,5.8)
  rrect25% 0.4x0.8 smd paste+0 mask+0: 18(-1.285,-5.8) 19(-0.635,-5.8) 20(0.015,-5.8) 21(0.665,-5.8) 22(1.315,-5.8) 23(1.965,-5.8) 24(2.615,-5.8) 25(3.265,-5.8) 26(3.915,-5.8) 45(3.915,5.8) 46(3.265,5.8) 47(2.615,5.8) 48(1.965,5.8) 49(1.315,5.8) 50(0.665,5.8) 51(0.015,5.8) 52(-0.635,5.8) 53(-1.285,5.8)
  rrect1% 7.8x10.2 smd paste-1000 mask+0: 55(1.25,0)
  silkscreen extent -6.28,-6.05 -2.78,6.74, body extent -6.3,-6.3 6.3,6.3, height 0.25
WE-LQS_2010 [mm] "SMD, 2-Leads, Body 2x1.6mm"
  rrect12% 0.85x1.2 smd: 1(-0.775,0) 2(0.775,0)
  body extent -1,-0.82 1,0.8, height 0.98
WEEE_Minimum [mm] "WEEElie bin"
  silkscreen extent -2.42,-4.38 2.52,2.65

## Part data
C1 C3 C4 C5 C16 C17 C25 C29 C30 C41 C42: library part CMP-0006752-5, "CAP, CERM, 0.1 uF, 25 V, +/- 5%, X7R, 0603", Cap_Case=0603, Manufacturer=AVX, Supplier Part Number 1=478-3713-1-ND, TempCo=X7R, Tolerance_%=5%, Value1="0.05 ohm", Value2=25V, ValueDisplayed=0.1uF
C2 C24: library part CMP-0007025-4, "CAP, CERM, 1.5 uF, 16 V, +/- 10%, X6S, 0603", Cap_Case=0603, Manufacturer=TDK, Supplier Part Number 1=445-14211-1-ND, TempCo=X6S, Tolerance_%=10%, Value1="0.009039 ohm", Value2=16V, ValueDisplayed=1.5uF
C6 C7 C10 C31 C32 C35: library part CMP-0075366-3, "CAP, CERM, 2.2 µF, 25 V,+/- 10%, X7S, 0603", Cap_Case=0603, Manufacturer=MuRata, Supplier Part Number 1=490-12732-1-ND, TempCo=X7S, Tolerance_%=10%, Value2=25V, ValueDisplayed=2.2µF
C8 C33: library part CMP-0080092-1, "CAP, CERM, 1000 pF, 25 V,+/- 1%, C0G/NP0, 0603", Cap_Case=0603, Manufacturer=Kemet, Supplier Part Number 1=399-7825-1-ND, TempCo=C0G/NP0, Tolerance_%=1%, Value2=25V, ValueDisplayed=1000pF
C9 C34: library part CMP-0007185-4, "CAP, CERM, 150 pF, 50 V, +/- 5%, C0G/NP0, 0603", Cap_Case=0603, Manufacturer=MuRata, Supplier Part Number 1=490-1431-1-ND, TempCo=C0G/NP0, Tolerance_%=5%, Value1=Unknown, Value2=50V, ValueDisplayed=150pF
C11 C36: library part CMP-0008342-2, "CAP, CERM, 2.2 uF, 25 V, +/- 10%, X7R, 0805", Alternate Manufacturer=Murata, Alternate PartNumber=GRM219R61E225KA12D, Cap_Case=0805, Manufacturer=MuRata, Supplier Part Number 1=490-3331-1-ND, TempCo=X7R, Tolerance_%=10%, Value1="0.005 ohm", Value2=25V, ValueDisplayed=2.2uF
C12 C14 C37 C39: library part CMP-0006985-4, "CAP, CERM, 3300 pF, 50 V, +/- 10%, X7R, 0603", Cap_Case=0603, Manufacturer=Kemet, Supplier Part Number 1=399-5339-1-ND, TempCo=X7R, Tolerance_%=10%, Value1=Unknown, Value2=50V, ValueDisplayed=3300pF
C13 C20 C38 C45: library part CMP-0079721-1, "CAP, CERM, 0.01 µF, 25 V,+/- 10%, X7R, 0603", Cap_Case=0603, Manufacturer="Presidio Components", TempCo=X7R, Tolerance_%=10%, Value2=25V, ValueDisplayed=0.01µF
C15 C40: library part CMP-0008183-2, "CAP, CERM, 10 uF, 25 V, +/- 20%, B, 0805", Cap_Case=0805, Manufacturer=MuRata, TempCo=B, Tolerance_%=20%, Value1=Unknown, Value2=25V, ValueDisplayed=10uF
C18 C19 C43 C44: library part CMP-0006894-4, "CAP, CERM, 220 pF, 50 V, +/- 10%, C0G/NP0, 0603", Cap_Case=0603, Manufacturer=Kemet, Supplier Part Number 1=399-1065-1-ND, TempCo=C0G/NP0, Tolerance_%=10%, Value1=Unknown, Value2=50V, ValueDisplayed=220pF
C22 C23 C27 C28: library part CMP-0009326-2, "CAP, CERM, 0.1 uF, 1000 V, +/- 10%, X7R, 1812", Cap_Case=1812, Manufacturer=Kemet, Supplier Part Number 1=399-6523-1-ND, TempCo=X7R, Tolerance_%=10%, Value1=Unknown, Value2=1000V, ValueDisplayed=0.1uF
D1 D2: library part CMP-0093310-1, "Standard LEDs - SMD Green TOPLED E 1608", Color=Green, Forward Current=2mA, Manufacturer="Osram Opto", Mouser Part Number=720-KGDELLS122A4849, Operating Temperature Range="-40°C to +110°C"
FID1 FID2 FID3: library part CMP-0077181-1, "Fiducial mark.  There is nothing to buy or mount.", Manufacturer=N/A
J1: library part CMP-0055334-1, "Header, 2.54mm, 6x1, Gold, R/A, TH", Color=Black, Current_A=3A, Manufacturer=Molex, Supplier Part Number 1=WM8112-ND, Voltage_V=350V
J2 J3: library part CMP-0075320-1, "Receptacle, Ultra Miniature Coaxial, Male Pin, 50 ohm, SMT", Color=Beige, Manufacturer="Hirose Electric Co. Ltd.", Supplier Part Number 1=H122041-ND
L1 L2: library part CMP-0063789-1, "Inductor, 10 uH, 0.5 A, 0.85 ohm, SMD", Manufacturer="Wurth Elektronik", Value1="0.85 ohm", Value2=0.5A, ValueDisplayed=10uH
LOGO1: library part CMP-0074837-1, "IEC 61010-1 Hot Surface Warning"
LOGO3: library part CMP-0074835-1, "IEC 61010-1 High Voltage Warning"
Logo5: library part CMP-0074844-1
Logo6: library part CMP-0074847-1, "FCC_disclaimer"
Logo8: library part CMP-0074769-1
MP1: library part CMP-0093659-2, "Heat Sink Assorted (BGA, LGA, CPU, ASIC...) Aluminum - Top Mount", Digikey Part Number=294-1162-ND, Manufacturer=CTS, Mating Package=BGA, Mouser Part Number=774-APF404013CB/A01, Natural Thermal Resistance=9.9°C/W, Operating Temperature Range=to, Thermal Resistance Forced Air Flow=2.3°C/W
R1 R4 R15: library part CMP-0022779-5, "RES, 12.0 k, 1%, 0.1 W, 0603", Manufacturer=Yageo, Power_W=100mW, Supplier Part Number 1=311-12.0KHRCT-ND, TempCo="100 ppm/C", Tolerance_%=1%, Value2=0.1W, Value_Code=12k0, ValueDisplayed=12.0k
R2: library part CMP-0022996-5, "RES, 2.70 k, 1%, 0.1 W, 0603", Manufacturer=Yageo, Power_W=100mW, Supplier Part Number 1=311-2.70KHRCT-ND, TempCo="100 ppm/C", Tolerance_%=1%, Value2=0.1W, Value_Code=2k70, ValueDisplayed=2.70k
R3 R14: library part CMP-0025899-5, "RES, 1.0 k, 5%, 0.1 W, 0603", Manufacturer=Yageo, Power_W=100mW, Supplier Part Number 1=311-1.0KGRCT-ND, TempCo="100 ppm/C", Tolerance_%=5%, Value2=0.1W, Value_Code=1k00, ValueDisplayed=1.0k
R5 R7 R9 R16 R17 R19: library part CMP-0080488-1, "RES, 10.0 k, 1%, 0.1 W, 0603", Manufacturer="TT Electronics/IRC", Power_W=100mW, TempCo="100 ppm/C", Tolerance_%=1%, Value2=0.1W, Value_Code=10k0, ValueDisplayed=10.0k
R6 R24 R25 R26: library part CMP-0025696-3, "RES, 4.7 k, 5%, 0.1 W, 0603", Manufacturer=Bourns, Power_W=100mW, Supplier Part Number 1=CR0603-JW-472GLFCT-ND, TempCo="200 ppm/C", Tolerance_%=5%, Value2=0.1W, Value_Code=4k70, ValueDisplayed=4.7k
R8 R18: library part CMP-0023037-5, "RES, 33.0 k, 1%, 0.1 W, 0603", Manufacturer=Yageo, Power_W=100mW, Supplier Part Number 1=311-33.0KHRCT-ND, TempCo="100 ppm/C", Tolerance_%=1%, Value2=0.1W, Value_Code=33k0, ValueDisplayed=33.0k
R10 R20: library part CMP-0025933-5, "RES, 5.6 k, 5%, 0.1 W, 0603", Manufacturer=Yageo, Power_W=100mW, Supplier Part Number 1=311-5.6KGRCT-ND, TempCo="100 ppm/C", Tolerance_%=5%, Value2=0.1W, Value_Code=5k60, ValueDisplayed=5.6k
R11 R21: library part CMP-0022993-5, "RES, 2.61 k, 1%, 0.1 W, 0603", Manufacturer=Yageo, Power_W=100mW, Supplier Part Number 1=311-2.61KHRCT-ND, TempCo="100 ppm/C", Tolerance_%=1%, Value2=0.1W, Value_Code=2k61, ValueDisplayed=2.61k
R12 R13 R22 R23: library part CMP-0023188-5, "RES, 56.0, 1%, 0.1 W, 0603", Manufacturer=Yageo, Power_W=100mW, Supplier Part Number 1=311-56.0HRCT-ND, TempCo="100 ppm/C", Tolerance_%=1%, Value2=0.1W, Value_Code=56R0, ValueDisplayed=56.0
TP1 TP2 TP3 TP4 TP5 TP6: library part CMP-0055044-1, "PCB Pin, 0.04\" DIA, Edge-Mount", Manufacturer=Mill-Max, Supplier Part Number 1=ED1278-ND
TP7: library part CMP-0055142-1, "Test Point, Compact, Red, TH", Color=Red, Manufacturer=Keystone, Supplier Part Number 1=36-5005-ND
TP8 TP10 TP12: library part CMP-0055138-1, "Test Point, Miniature, Black, TH", Color=Black, Manufacturer=Keystone, Supplier Part Number 1=36-5001-ND
TP9: library part CMP-0055145-1, "Test Point, Compact, Orange, TH", Color=Orange, Manufacturer=Keystone, Supplier Part Number 1=36-5008-ND
TP11: library part CMP-0055143-1, "Test Point, Compact, Black, TH", Color=Black, Manufacturer=Keystone, Supplier Part Number 1=36-5006-ND
U1: library part CMP-0054374-1, "Dual 4-Input Positive-AND Gates, D0014A, TUBE", F @ Nom Voltage(Max)(Mhz)=125, Generic Part Number=SN74AS21, ICC @ Nom Voltage(Max)(mA)=0.0014, Manufacturer="Texas Instruments", Operating Temperature Range(C)="0 to 70", Rating=Catalog, tpd @ Nom Voltage(Max)(ns)=15, Voltage(Nom)(V)=5
U2 U5: library part CMP-0093317-1, "1W, 15V-Vin, 15V-Vout, High-Efficiency, >3 kVRMS Isolated DC-DC Converter", Manufacturer="Texas Instruments", Max Power Dissipation=540mW, Max Supply Voltage=27V, Min Supply Voltage=10V, Operating Temperature Range="-40°C to +150°C", Output Voltage=2.5-17V
U3 U6: library part CMP-0088545-3, "600-V 30-mΩ Integrated GaN Power Stage with Smart Driver", Manufacturer="Texas Instruments", Max Supply Voltage=18V, Min Supply Voltage=7.5V, Nominal Supply Current=13mA, Operating Temperature Range="-40°C to +125°C", Output Voltage=480V, Part Number=LMG3425R030RQZT
U4 U7: library part CMP-04872-000092-1, "DGTL ISO 5000VRMS 4CH GP 16SOIC", Case/Package=SOIC, Manufacturer="Texas Instruments", Max Operating Temperature=125°C, Max Supply Voltage=5.5V, Min Operating Temperature=-55°C, Min Supply Voltage=2.25V
ZZ1: library part CMP-0077236-1
ZZ2: library part CMP-0077237-1
ZZ3: library part CMP-0077238-1

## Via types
v1: diameter 0.61, hole 0.203, Top Layer to Bottom Layer, tented both sides, 497 vias
v2: diameter 0.61, hole 0.305, Top Layer to Bottom Layer, tented both sides, 16 vias

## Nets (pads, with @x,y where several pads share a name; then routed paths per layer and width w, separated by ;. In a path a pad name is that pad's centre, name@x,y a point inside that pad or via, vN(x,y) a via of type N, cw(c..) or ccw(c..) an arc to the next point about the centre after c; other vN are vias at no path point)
5V_HS: C2.2 C4.1 C10.1 C17.1 R3.2 R7.2 U4.1 U4.7 | length 35.5
  Top Layer w0.508: R7.2@46.147,34.783 46.128,34.802 44.653,34.802 C10.1@44.449,34.802 44.653,35.006 44.653,36.349 44.825,36.52 45.07,36.52 45.548,36.52 ; C2.2@46.657,38.152 46.838,37.971 46.838,36.729 R3.2@47.047,36.52 ; R3.2@47.072,36.52 R3.2@47.047,36.52 ; C17.1@50.564,55.85 51.897,55.85 51.969,55.778 v2(51.996,55.778) 52.024,55.778 52.149,55.653 U4.1@53.798,55.653 ; U4.7@53.798,48.033 53.702,47.937 v2(51.164,47.937) 50.575,47.348 50.575,46.141 45.558,41.123 45.558,36.53 45.548,36.52 ; 45.548,36.52 46.826,36.52 R3.2@47.047,36.52
  MidLayer2 w0.508: v2(51.164,47.937) 51.164,50.978 51.713,51.527 51.713,54.541 51.996,54.824 v2(51.996,55.778)
5V_ISO: C1.1 C16.1 C41.1 J1.4 R4.1 R15.2 U1.14 U4.16 U7.16 | length 82.1
  Top Layer w0.508: U7.16@62.74,29.963 64.175,29.963 64.542,30.329 C41.1@65.415,30.329 66.774,31.688 67.261,31.688 ; U4.16@62.929,55.653 65.422,55.653 65.492,55.723 65.517,55.723 65.738,55.944 C16.1@65.738,55.969 65.776,56.007 v2(67.261,56.007) ; R15.2@65.534,16.646 65.534,16.621 67.294,14.861 v2(69.162,14.861) ; R4.1@67.561,33.125 67.566,33.121 67.566,31.993 67.261,31.688 ; v1(71.874,31.396) 69.81,31.396 67.553,31.396 67.261,31.688 ; v2(72.133,25.018) 73.181,25.018 C1.1@73.381,25.218 73.402,25.197 U1.14@73.402,23.356
  MidLayer2 w0.508: J1.4@65.311,4.242 67.001,5.932 69.572,8.502 69.572,14.451 v2(69.162,14.861) 70.49,16.189 70.49,24.696 70.651,24.857 70.651,25.018 ; v2(67.261,56.007) 70.651,52.617 70.651,31.276 ; v1(71.874,31.396) 70.772,31.396 70.651,31.276 ; v2(72.133,25.018) 70.651,25.018 ; 70.651,25.018 70.651,31.276
5V_LS: C24.2 C29.1 C35.1 C42.1 R14.2 R17.2 U7.1 U7.7 | length 39.2
  Top Layer w0.254: R17.2@45.981,12.706 R17.2@45.996,12.691 R14.2@47.853,12.691 C24.2@47.853,14.306 ; C24.2@47.853,14.346 C24.2@47.853,14.306 ; v1(49.276,29.174) 49.547,29.444 C42.1@50.39,29.444 51.214,29.444 51.733,29.963 U7.1@53.609,29.963 ; U7.7@53.609,22.343 53.539,22.273 51.872,22.273 v1(51.808,22.209) 45.509,22.209 42.451,19.151 42.451,14.993 43.099,14.346 44.382,14.346 45.981,14.346 46.02,14.306 C24.2@47.853,14.306
  MidLayer2 w0.254: v1(49.276,29.174) 49.276,28.55 51.088,26.738 51.088,26.153 52.559,24.682 52.559,24.471 51.808,23.72 v1(51.808,22.209)
12V_HS: C2.1 C5.1 C7.1 C15.1 R5.1 U2.28 U2.29 U3.46 | length 23.6
  Top Layer w0.254: U3.46@36.596,36.635 38.237,36.635 C15.1@38.555,36.317
  Top Layer w0.45: C5.1@51.654,38.602 52.115,38.602 ; U2.29@53.286,37.952 52.279,37.952 52.095,38.136 52.095,38.583 52.115,38.602 ; U2.28@53.286,38.602 52.115,38.602
  Top Layer w0.508: C15.1@38.555,36.317 v2(39.734,36.317) ; C2.1@46.578,39.673 C2.1@46.657,39.752 47.186,39.223 47.694,39.223 47.745,39.273 R5.1@48.296,39.273 ; v1(48.479,38.114) 48.479,39.09 R5.1@48.296,39.273 ; C5.1@51.462,38.769 C5.1@51.462,38.794 ; C5.1@51.654,38.602 C5.1@51.462,38.794 ; R5.1@48.296,39.273 49.189,39.273 49.889,39.973 C7.1@49.889,39.998 50.418,39.469 50.812,39.469 51.462,38.819 C5.1@51.462,38.794
  MidLayer2 w0.508: v2(39.734,36.317) 46.682,36.317 v1(48.479,38.114)
12V_ISO: C6.1 C9.1 C31.1 C34.1 J1.5 R1.2 U2.6 U2.7 U5.6 U5.7 | length 65.9
  Top Layer w0.508: U5.7@63.026,11.382 63.668,11.382 64.068,10.982 65.114,10.982 ; U2.6@63.236,36.652 64.237,36.652 64.569,36.983 64.569,37 ; U2.7@63.236,37.302 64.266,37.302 64.569,37 ; C34.1@65.114,12.264 65.114,10.982 ; C31.1@66.841,12.264 66.841,11.28 v2(66.672,11.111) 66.543,10.982 65.114,10.982 ; R1.2@72.046,36.307 72.046,37.029 71.63,37.446 v1(68.324,37.446) 67.323,37.446 C6.1@67.297,37.471 67.128,37.302 65.153,37.302 64.923,37.072 64.923,37 64.569,37
  MidLayer2 w0.508: J1.5@62.771,4.242 62.771,5.416 ; v2(66.672,11.111) 66.672,9.202 67.656,8.218 67.755,8.119 67.755,7.698 65.771,5.714 63.069,5.714 62.771,5.416 ; v1(68.324,37.446) 64.424,37.446 62.335,35.356 62.335,6.34 62.771,5.903 62.771,5.416
12V_LS: C24.1 C30.1 C32.1 C40.1 R16.1 U5.28 U5.29 U6.46 | length 23.5
  Top Layer w0.45: C30.1@51.138,12.735 51.731,12.735 ; 51.765,12.7 51.765,12.296 52.029,12.032 U5.29@53.076,12.032 ; 51.784,12.682 U5.28@53.076,12.682
  Top Layer w0.508: U6.46@36.575,21.15 37.333,21.15 37.399,21.084 v1(39.637,21.084) ; v2(45.789,20.581) 45.808,20.562 46.091,20.562 46.801,19.853 47.642,19.011 47.642,17.872 R16.1@47.822,17.692 47.872,17.642 47.872,15.964 C24.1@47.853,15.946 47.853,15.921 48.074,15.7 48.173,15.7 49.563,14.31 C30.1@51.138,12.735
  MidLayer2 w0.508: v1(39.637,21.084) 40.797,21.084 41.299,20.581 v2(45.789,20.581)
EN_Supply_Driver: C13.1 C38.1 R1.1 R2.2 U2.4 U5.4 | length 43.5
  Top Layer w0.381: U5.4@63.026,9.432 63.041,9.447 65.287,9.447 C38.1@65.322,9.413 ; U2.4@63.236,35.352 v1(64.886,35.352) 66.194,35.352 C13.1@66.269,35.277 66.269,34.726 66.678,34.317 69.81,34.317 R2.2@69.81,34.707 R1.1@72.046,34.707 ; v1(65.311,7.482) C38.1@65.311,9.413
  MidLayer2 w0.254: v1(64.886,35.352) 64.868,35.352 64.136,34.619 64.136,31.945 63.503,31.313 63.503,22.108 64.474,21.137 64.474,19.631 64.389,19.547 64.389,11.184 65.311,10.262 v1(65.311,7.482)
F\A\U\L\T\_\H\S\_\I\S\O\: R6.2 U1.5 U4.13 | length 48.5
  Top Layer w0.254: U4.13@62.929,51.843 62.937,51.835 v1(66.84,51.835) ; U1.5@67.952,18.276 67.986,18.309 v1(69.217,18.309) ; v1(71.625,48.202) 73.446,48.202 R6.2@73.455,48.193
  MidLayer2 w0.254: v1(66.84,51.835) 69.969,48.706 69.969,19.062 v1(69.217,18.309)
  Bottom Layer w0.254: v1(66.84,51.835) 67.992,51.835 v1(71.625,48.202)
F\A\U\L\T\_\L\S\_\I\S\O\: R26.2 U1.1 U7.13 | length 19.7
  Top Layer w0.254: U7.13@62.74,26.153 64.506,26.153 v1(64.784,26.432) ; U1.1@67.952,23.356 68.873,23.356 71.069,21.16 71.069,16.697 72.029,15.737 72.029,15.246 R26.2@73.622,13.653
  Top Layer w0.508: v1(66.821,23.459) 66.848,23.459 66.951,23.356 U1.1@67.952,23.356
  MidLayer2 w0.254: v1(64.784,26.432) 66.821,24.395 v1(66.821,23.459)
GND_ISO: C1.2 C6.2 C9.2 C13.2 C16.2 C19.2 C20.2 C31.2 C34.2 C38.2 C41.2 C44.2 C45.2 J1.6 J2.2@70.51,55.431 J2.3@70.51,52.481 J3.2@69.162,28.543 J3.3@69.162,25.593 R2.1 R6.1 R24.1 R25.1 R26.1 TP12.1 U1.7 U1.9 U1.10 U1.12 U1.13 U2.1 U2.2 U2.5 U2.8 U2.9 U2.10 U2.11 U2.12 U2.13 U2.14 U2.15 U2.16 U2.17 U2.18 U4.9 U4.15 U5.1 U5.2 U5.5 U5.8 U5.9 U5.10 U5.11 U5.12 U5.13 U5.14 U5.15 U5.16 U5.17 U5.18 U7.9 U7.15 | length 45.5
  Top Layer w0.254: U7.15@62.74,28.693 v1(66.56,28.693) ; U5.5@63.026,10.082 64.444,10.082 64.516,10.154 66.441,10.154 66.458,10.138 66.773,10.138 66.922,9.989 C38.2@66.922,9.413 66.951,9.383 v1(66.951,7.882) ; U2.5@63.236,36.002 64.933,36.002 v1(65.238,36.307) ; C13.2@67.869,35.277 67.837,35.309 v1(67.837,36.251) 69.754,36.251 R2.1@69.81,36.307 ; v1(72.398,27.875) 72.398,27.802 C1.2@73.381,26.818
  Top Layer w0.635: U4.9@62.929,46.763 62.93,46.763 62.937,46.757 v1(62.937,46.058) ; U4.15@62.929,54.383 65.723,54.383 C16.2@65.738,54.369 ; v1(64.542,22.91) 65.396,22.91 65.415,22.891 65.44,22.891 65.598,22.734 C45.2@65.598,22.709 ; C44.2@65.977,26.368 66.121,26.224 66.528,26.224 66.678,26.074 67.356,26.074 67.837,25.593 J3.3@69.162,25.593 ; v1(66.951,16.322) 66.976,16.322 67.562,15.736 U1.7@67.952,15.736 ; C19.2@68.262,49.763 C20.2@68.262,48.033 68.285,48.01 v1(68.285,47) 68.285,46.639 69.144,45.78 R24.1@69.169,45.78 ; 68.388,29.988 69.162,29.214 J3.2@69.162,28.543 ; J2.3@70.51,52.481 72.415,52.481 v1(72.417,52.482) 73.455,51.445 R6.1@73.455,49.793 ; J2.2@70.51,55.431 72.26,55.431 v1(72.279,55.45) ; R25.1@71.63,12.053 72.603,12.053 v1(72.666,11.99) 72.73,12.053 R26.1@73.622,12.053 ; v1(72.256,17.013) 73.395,17.013 U1.9@73.402,17.006 ; v1(72.256,18.283) 73.395,18.283 U1.10@73.402,18.276 ; v1(72.256,20.823) 73.395,20.823 U1.12@73.402,20.816 ; v1(72.256,22.093) 73.395,22.093 U1.13@73.402,22.086
  other v1: 63.758,6.412 64.352,6.882 67.945,8.917 67.952,10.052 67.952,13.786 68.873,13.786 66.116,14.614 65.519,15.146 63.166,19.234 63.902,19.868 63.166,20.302 67.462,25.968 67.415,28.707 66.976,29.444 63.236,31.993 63.236,32.802 66.732,40.068 65.417,40.184 64.746,40.247 66.074,40.451 66.732,40.718 65.417,40.834 64.746,40.948 66.074,41.101 66.732,41.368 65.417,41.484 64.746,41.649 66.074,41.751 66.719,42.003 65.417,42.134 64.746,42.35 66.061,42.386 66.732,42.668 65.403,42.769 64.746,43.05 66.074,43.051 66.719,43.303 65.417,43.434 66.061,43.686 64.746,43.751 65.403,44.069 64.746,44.452 64.73,54.383
High_Rail: C22.1 C23.1 C27.1 C28.1 TP1.1 TP2.1 TP7.1 U3.2 U3.3 U3.4 U3.5 U3.6 U3.7 U3.8 U3.9 U3.10 U3.11 U3.12 U3.13 U3.14 U3.15 | length 14.6
  Top Layer w0.508: TP7.1@12.497,52.73 15.471,52.73 20.692,47.51 C28.1@24.982,47.51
